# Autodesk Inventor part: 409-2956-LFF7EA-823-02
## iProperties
Created: 2010-11
Part Number: 409-2956-LFF7EA-823-02
Material: 3/8" OD TUBE - SS
Document SubType Name: Modeling
Designer: S. Boerckel
Engineer: Steve Boerckel
Mass: 285.633 g
Surface Area: 619.161 cm^2
Volume: 35.3507 cm^3
Density: 8.08 g/cm^3
Description: PRESSURE DIFF TUBE
Length: 59.146 in
Author: S. Boerckel
Revision Number: 0
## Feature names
1. Sweep3
